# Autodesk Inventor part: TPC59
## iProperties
Shininess: 64.0
Length Units: 11272
Angle Units: 11279
Time Units: 11290
Mass Units: 11286
Length Display Precision: 3
Angle Display Precision: 2
Compacted: True
Part Number: TPC59
Document SubType Name: Modeling
Created: 2004-08
Designer: Lori
Manufacturer: Standard
Standards Organization: Custom
Density: 0.0
Volumn: 0.0
Area: 0.0
PropertySet Name: Model Information
Control State: 0
Master: False
Checked Out: False
Author: Lori
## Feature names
1. Base1
